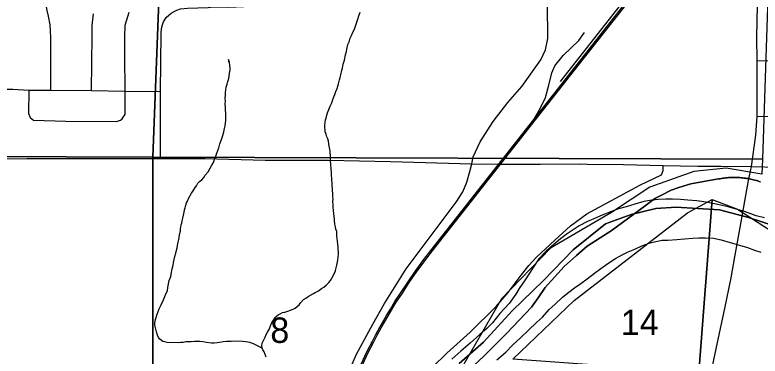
# Model space of a CAD drawing. Extents: x 0 to 34, y 0 to 22.
# Drawn here: x 3.784 to 5.012, y 16.149 to 16.711 of the extents above; entities that cross this region are included whole.
import ezdxf

# ---------------------------------------------------------------- set-up
doc = ezdxf.new("R2010")
doc.units = 0
for name, color, linetype in [('GM_X_City_Street', 7, 'Continuous'), ('GM_X_Major_River', 7, 'Continuous'), ('GM_X_Minor_River', 7, 'Continuous'), ('GM_X_Rail_Line', 7, 'Continuous'), ('GM_X_Section', 7, 'Continuous'), ('GM_X_Section_Text', 7, 'Continuous'), ('GM_X_State_Route', 7, 'Continuous'), ('GM_X_Township_Road', 7, 'Continuous'), ('SC_Shading3', 7, 'Continuous')]:
    doc.layers.add(name, color=color, linetype=linetype)

msp = doc.modelspace()

# ---------------------------------------------------------------- linework, layer by layer
at = {"layer": 'GM_X_City_Street'}
msp.add_line((4.9974, 16.4615), (5.0659, 16.4601), dxfattribs=at)
for points in [[(4.9974, 16.4615), (5.005, 16.5132), (5.007, 16.5445), (5.007, 16.6363), (5.0063, 16.6742), (5.0073, 16.7276), (5.0069, 16.7711), (5.0073, 16.8306), (5.0074, 16.8807), (5.0074, 16.9361), (5.0085, 17.0093), (5.0084, 17.0455), (5.0085, 17.0995), (5.0087, 17.1373), (5.0087, 17.1382)], [(4.5369, 16.4661), (4.5393, 16.4773), (4.5507, 16.5023), (4.572, 16.5358), (4.596, 16.5667), (4.6195, 16.5934), (4.6506, 16.6374), (4.6581, 16.6535), (4.6621, 16.6725), (4.6616, 16.729), (4.6616, 16.7781), (4.662, 16.8232), (4.6625, 16.8735), (4.661, 16.9232), (4.66, 16.9414), (4.6593, 16.9843), (4.6593, 16.9858), (4.6596, 16.9959), (4.6608, 17.0518), (4.6594, 17.1049)], [(3.8432, 16.5874), (3.8431, 16.6538), (3.8431, 16.6736), (3.8427, 16.6854), (3.8422, 16.6951), (3.8396, 16.7091), (3.8374, 16.7184), (3.8352, 16.7307), (3.8343, 16.7662), (3.8344, 16.7836)], [(4.0291, 16.7001), (4.0335, 16.707), (4.0377, 16.7109), (4.0416, 16.7143), (4.0466, 16.717), (4.051, 16.7193), (4.0571, 16.7212), (4.0682, 16.7226), (4.1026, 16.7237), (4.111, 16.7245), (4.1365, 16.7243), (4.1736, 16.7255), (4.2216, 16.7283), (4.2461, 16.7296), (4.2634, 16.7301), (4.277, 16.731), (4.2958, 16.7305), (4.3292, 16.7305), (4.4594, 16.7293), (4.5138, 16.7285), (4.6085, 16.728), (4.6616, 16.729)], [(3.9105, 16.5865), (3.9112, 16.677), (3.9112, 16.6938), (3.9134, 16.7129)], [(3.9656, 16.547), (3.9656, 16.5856), (3.9654, 16.645), (3.9654, 16.6758), (3.966, 16.6944), (3.9725, 16.7161)], [(4.0242, 16.4747), (4.0237, 16.5852), (4.0248, 16.6809), (4.0254, 16.6888), (4.0271, 16.695), (4.0291, 16.7001)], [(5.007, 16.6363), (5.0671, 16.6349), (5.1257, 16.6339), (5.1862, 16.6323)], [(3.7121, 16.589), (3.7808, 16.5888), (3.8073, 16.5874), (3.8432, 16.5874), (3.9105, 16.5865), (3.9656, 16.5856), (4.0237, 16.5852)], [(3.8073, 16.5874), (3.8064, 16.5488), (3.8091, 16.5421), (3.8145, 16.5381), (3.8678, 16.5363), (3.9513, 16.5354), (3.958, 16.5381), (3.9607, 16.5399), (3.9625, 16.543), (3.9656, 16.547)], [(5.007, 16.5445), (5.067, 16.5438), (5.0948, 16.5433), (5.1245, 16.5423), (5.184, 16.5403)], [(3.7145, 16.4741), (3.8045, 16.4747), (4.0164, 16.4747), (4.0242, 16.4747), (4.0253, 16.4747)], [(4.0253, 16.4747), (4.0971, 16.4747), (4.1964, 16.4721), (4.3009, 16.4721), (4.4028, 16.4695), (4.5369, 16.4661), (4.5828, 16.4653), (4.6502, 16.4651), (4.7147, 16.4656), (4.7267, 16.4654)], [(4.2465, 16.0051), (4.249, 16.0069), (4.2886, 16.0363), (4.3032, 16.0547), (4.3197, 16.0901), (4.3471, 16.1524), (4.3736, 16.2015), (4.3929, 16.2355), (4.4288, 16.2927), (4.511, 16.4027), (4.5218, 16.4197), (4.5289, 16.4358), (4.5336, 16.4532), (4.5369, 16.4661)], [(4.4251, 16.0847), (4.4959, 16.1536), (4.534, 16.1884), (4.5771, 16.2306), (4.5965, 16.2535), (4.6165, 16.2804), (4.6309, 16.2983), (4.6435, 16.312), (4.6737, 16.3403), (4.6992, 16.3636), (4.7262, 16.3836), (4.8134, 16.4305), (4.8494, 16.4476), (4.852, 16.4548), (4.8519, 16.4633)], [(4.7267, 16.4654), (4.7868, 16.4646), (4.8519, 16.4633), (4.9094, 16.4621), (4.9475, 16.462), (4.9974, 16.4615)], [(4.9703, 16.3128), (4.9788, 16.3607), (4.9822, 16.3797), (4.9927, 16.4385), (4.9974, 16.4615)], [(4.8397, 15.4527), (4.8456, 15.4697), (4.855, 15.5142), (4.8617, 15.5929), (4.869, 15.6599), (4.8767, 15.7363), (4.8851, 15.8274), (4.8906, 15.8858), (4.8915, 15.8956), (4.8959, 15.9365), (4.9, 15.9686), (4.9055, 15.9974), (4.9143, 16.0411), (4.9265, 16.101), (4.9418, 16.1711), (4.9536, 16.2272), (4.9641, 16.2778), (4.9703, 16.3128)]]:
    msp.add_lwpolyline(points, dxfattribs=at)
at = {"layer": 'GM_X_Major_River'}
for points in [[(5.0191, 16.3771), (5.0055, 16.3804), (4.9863, 16.3872), (4.9723, 16.3909), (4.9591, 16.395), (4.9493, 16.3971), (4.9364, 16.4), (4.9232, 16.4025), (4.9077, 16.4051), (4.8926, 16.4061), (4.8808, 16.4068), (4.8675, 16.4074), (4.8565, 16.4076), (4.8444, 16.4071), (4.8334, 16.4062), (4.8204, 16.4037), (4.8055, 16.3995), (4.791, 16.3952), (4.7785, 16.3916), (4.7655, 16.3869), (4.7517, 16.3815), (4.7379, 16.3753), (4.7276, 16.3706), (4.7138, 16.3636), (4.7019, 16.3559), (4.6923, 16.3496), (4.6827, 16.3425), (4.6722, 16.3329), (4.6591, 16.3217), (4.6471, 16.3094), (4.6366, 16.2936), (4.6248, 16.2748), (4.6147, 16.2606), (4.6092, 16.2508), (4.5983, 16.2358), (4.5831, 16.2194), (4.5711, 16.204), (4.5614, 16.1943), (4.5498, 16.1847), (4.5344, 16.1705), (4.5186, 16.1571), (4.5039, 16.1441)], [(4.5779, 16.1427), (4.5929, 16.1553), (4.6045, 16.1676), (4.6173, 16.1792), (4.6304, 16.1919), (4.6435, 16.2041), (4.6532, 16.2131), (4.6645, 16.2258), (4.6741, 16.2347), (4.6865, 16.2463), (4.6965, 16.2541), (4.7061, 16.2615), (4.7165, 16.2685), (4.7269, 16.2763), (4.7392, 16.2856), (4.7496, 16.2933), (4.7608, 16.3015), (4.7734, 16.3096), (4.7846, 16.3159), (4.7942, 16.3206), (4.8052, 16.3253), (4.8171, 16.3308), (4.8305, 16.3355), (4.84, 16.338), (4.8503, 16.34), (4.8598, 16.3402), (4.8746, 16.3411), (4.8875, 16.3424), (4.9012, 16.3436), (4.9111, 16.3438), (4.9217, 16.344), (4.935, 16.3433), (4.9478, 16.3408), (4.9625, 16.336), (4.978, 16.3319), (4.9912, 16.3278), (5.0025, 16.3238), (5.013, 16.3202)]]:
    msp.add_lwpolyline(points, dxfattribs=at)
at = {"layer": 'GM_X_Minor_River'}
for points in [[(4.3062, 16.2776), (4.3098, 16.2848), (4.3122, 16.2893), (4.3126, 16.2923), (4.3143, 16.2991), (4.316, 16.307), (4.3169, 16.3123), (4.317, 16.3169), (4.3166, 16.3283), (4.3163, 16.3336), (4.3157, 16.3386), (4.3147, 16.347), (4.3144, 16.3508), (4.3142, 16.3542), (4.3127, 16.3584), (4.3124, 16.3622), (4.3114, 16.3664), (4.3108, 16.3722), (4.3105, 16.3752), (4.3095, 16.3832), (4.3087, 16.3946), (4.3084, 16.3988), (4.3081, 16.4034), (4.3083, 16.4083), (4.308, 16.4114), (4.3077, 16.4148), (4.3075, 16.4239), (4.3069, 16.43), (4.307, 16.4338), (4.3063, 16.4388), (4.3061, 16.443), (4.3058, 16.446), (4.3056, 16.4529), (4.3049, 16.4567), (4.3047, 16.4654), (4.3041, 16.4704), (4.3042, 16.4734), (4.3039, 16.4795), (4.3033, 16.4845), (4.3034, 16.4875), (4.302, 16.4948), (4.3014, 16.4986), (4.3007, 16.5032), (4.2997, 16.507), (4.2982, 16.5101), (4.2968, 16.5147), (4.2954, 16.5185), (4.2951, 16.5219), (4.2948, 16.5253), (4.2949, 16.5284), (4.2954, 16.5341), (4.2959, 16.5382), (4.2967, 16.5413), (4.298, 16.5462), (4.2992, 16.5499), (4.3012, 16.5556), (4.3036, 16.5609), (4.3061, 16.5665), (4.3081, 16.5718), (4.3097, 16.5763), (4.3114, 16.5804), (4.3126, 16.5853), (4.315, 16.5902), (4.3162, 16.594), (4.3171, 16.5978), (4.3188, 16.6042), (4.32, 16.608), (4.3213, 16.6125), (4.3226, 16.6204), (4.3238, 16.6234), (4.3251, 16.6299), (4.3272, 16.637), (4.3289, 16.6457), (4.3306, 16.651), (4.3311, 16.6548), (4.3328, 16.6624), (4.3352, 16.668), (4.336, 16.6718), (4.3385, 16.6774), (4.3413, 16.6842), (4.3433, 16.688), (4.3474, 16.6993), (4.349, 16.7042), (4.3507, 16.7098), (4.3527, 16.7159)], [(4.1313, 16.5579), (4.1307, 16.5655), (4.1308, 16.5685), (4.1306, 16.5743), (4.1311, 16.5792), (4.1312, 16.5834), (4.1321, 16.5925), (4.1338, 16.5974), (4.135, 16.6015), (4.1363, 16.6064), (4.1372, 16.6106), (4.1376, 16.6151), (4.1385, 16.62), (4.1386, 16.6238), (4.1384, 16.6284), (4.1377, 16.633), (4.1359, 16.638), (4.1361, 16.6335)], [(4.1915, 16.1622), (4.1773, 16.1694), (4.1712, 16.1715), (4.1648, 16.1724), (4.1595, 16.1729), (4.1454, 16.1733), (4.1405, 16.173), (4.1325, 16.1728), (4.1271, 16.1722), (4.1214, 16.1712), (4.1172, 16.1709), (4.1123, 16.1703), (4.1081, 16.1704), (4.0997, 16.1714), (4.0937, 16.1723), (4.0887, 16.1728), (4.08, 16.173), (4.0747, 16.1727), (4.069, 16.1725), (4.0655, 16.1722), (4.0613, 16.1715), (4.0575, 16.1713), (4.0545, 16.171), (4.0347, 16.1714), (4.0309, 16.1723), (4.0279, 16.1728), (4.023, 16.1767), (4.0208, 16.1798), (4.019, 16.1832), (4.0173, 16.189), (4.0155, 16.1955), (4.0145, 16.2001), (4.0146, 16.2039), (4.0155, 16.2095), (4.0184, 16.2182), (4.022, 16.2269), (4.0252, 16.2336), (4.0288, 16.2415), (4.0324, 16.2498), (4.0353, 16.2573), (4.0358, 16.2619), (4.0384, 16.2736), (4.0412, 16.28), (4.0416, 16.2838), (4.043, 16.2929), (4.0451, 16.2989), (4.0456, 16.3034), (4.0477, 16.3129), (4.0493, 16.3186), (4.0498, 16.3216), (4.0515, 16.3276), (4.0519, 16.331), (4.0532, 16.3367), (4.0541, 16.3409), (4.0545, 16.3439), (4.0554, 16.3496), (4.0567, 16.3549), (4.0568, 16.3587), (4.0581, 16.3651), (4.0589, 16.3681), (4.0598, 16.3719), (4.0607, 16.3764), (4.0619, 16.3813), (4.0628, 16.3863), (4.0637, 16.39), (4.0645, 16.3934), (4.0657, 16.3976), (4.067, 16.4014), (4.0686, 16.4044), (4.0702, 16.4085), (4.075, 16.4175), (4.0777, 16.4216), (4.0813, 16.4269), (4.0833, 16.4298), (4.0857, 16.434), (4.0884, 16.4369), (4.0919, 16.4395), (4.0954, 16.4432), (4.0978, 16.447), (4.1025, 16.4529), (4.106, 16.4589), (4.1084, 16.4638), (4.1112, 16.4679), (4.1137, 16.4747), (4.1153, 16.4785), (4.1169, 16.4837), (4.1185, 16.4879), (4.1202, 16.4924), (4.1219, 16.4988), (4.1243, 16.506), (4.1264, 16.5128), (4.1281, 16.5188), (4.1293, 16.5241), (4.1306, 16.5286), (4.131, 16.5324), (4.1316, 16.5377), (4.1317, 16.5419), (4.1318, 16.5465), (4.1315, 16.5495), (4.1312, 16.5541), (4.1313, 16.5579)], [(4.198, 16.1473), (4.1948, 16.1557), (4.1926, 16.1592), (4.1915, 16.1622), (4.1909, 16.1657), (4.1917, 16.1702), (4.1946, 16.1766), (4.1965, 16.1804), (4.1982, 16.1845), (4.2002, 16.1886), (4.2033, 16.1939), (4.2054, 16.1988), (4.2078, 16.2052), (4.2106, 16.2089), (4.2125, 16.2123), (4.2176, 16.2167), (4.2211, 16.2185), (4.2249, 16.2207), (4.2287, 16.2214), (4.2353, 16.2235), (4.2383, 16.2246), (4.2426, 16.2264), (4.246, 16.2282), (4.2522, 16.2333), (4.2554, 16.2374), (4.2593, 16.2423), (4.2643, 16.2448), (4.2674, 16.247), (4.2759, 16.2521), (4.279, 16.254), (4.284, 16.2565), (4.289, 16.2606), (4.2933, 16.2624), (4.2975, 16.2664), (4.3011, 16.2705), (4.3038, 16.2735), (4.3062, 16.2776)]]:
    msp.add_lwpolyline(points, dxfattribs=at)
at = {"layer": 'GM_X_Rail_Line'}
for points in [[(4.3543, 16.1358), (4.3639, 16.1559), (4.3731, 16.1736), (4.3789, 16.1845), (4.3854, 16.1966), (4.3962, 16.2157), (4.4027, 16.2262), (4.4102, 16.239), (4.4194, 16.2526), (4.4318, 16.2716), (4.4445, 16.29), (4.4578, 16.3081), (4.4696, 16.3232), (4.7042, 16.6217), (4.8478, 16.8047), (4.9534, 16.9393), (5.0803, 17.1004), (5.1191, 17.1499), (5.1842, 17.233), (5.3027, 17.3835), (5.4259, 17.5407), (5.4633, 17.5884)], [(5.1421, 17.1875), (5.1385, 17.1817), (5.1284, 17.1679), (4.9398, 16.929), (4.7753, 16.7196), (4.6823, 16.6015)], [(4.3565, 16.1348), (4.3662, 16.1548), (4.3753, 16.1724), (4.3811, 16.1833), (4.3876, 16.1954), (4.3983, 16.2144), (4.4048, 16.2249), (4.4123, 16.2376), (4.4214, 16.2512), (4.4339, 16.2702), (4.4465, 16.2886), (4.4598, 16.3066), (4.4715, 16.3217), (4.7062, 16.6202), (4.8497, 16.8032), (4.9554, 16.9378), (5.0823, 17.0989)], [(4.6391, 16.5389), (4.6494, 16.557), (4.6585, 16.575), (4.6637, 16.5955), (4.6689, 16.616), (4.6736, 16.6276), (4.6871, 16.6443), (4.713, 16.669), (4.7226, 16.6821)]]:
    msp.add_lwpolyline(points, dxfattribs=at)
at = {"layer": 'GM_X_Section'}
for points in [[(3.0196, 17.4831), (3.1709, 17.4714), (4.0485, 17.4495), (4.0113, 16.4768), (3.0135, 16.4807)], [(4.0485, 17.4495), (5.0461, 17.3925), (5.016, 16.4735), (4.0113, 16.4768)], [(3.0135, 16.4807), (4.0113, 16.4768), (4.0112, 15.46), (3.0168, 15.4789)], [(4.0113, 16.4768), (5.016, 16.4735), (5.0144, 16.4489), (4.9559, 16.4588), (4.9027, 16.4533), (4.8303, 16.4274), (4.767, 16.3854), (4.6663, 16.3267), (4.586, 16.2434), (4.5198, 16.1291), (4.4237, 16.0287), (4.3302, 15.9111), (4.264, 15.7957), (4.2171, 15.6985), (4.1382, 15.5716), (4.0543, 15.4588), (4.0112, 15.46)], [(4.6046, 16.1438), (4.7052, 16.2404), (4.8924, 16.385), (4.9329, 16.4073), (4.9109, 16.1221)], [(4.9329, 16.4073), (4.9747, 16.391), (5.0349, 16.3524), (5.1555, 16.2978), (5.2124, 16.265), (5.3126, 16.2343), (5.437, 16.2217), (5.569, 16.217), (5.709, 16.1875), (5.8473, 16.1527), (5.9234, 16.1293), (5.9113, 16.0496), (4.9109, 16.1221)]]:
    msp.add_lwpolyline(points, close=True, dxfattribs=at)
at = {"layer": 'GM_X_State_Route'}
msp.add_lwpolyline([(4.5218, 16.1162), (4.5574, 16.1495), (4.5664, 16.1585), (4.5944, 16.1865), (4.635, 16.2298), (4.6459, 16.2452), (4.6578, 16.2621), (4.6788, 16.2853), (4.689, 16.2965), (4.7094, 16.3146), (4.7271, 16.3304), (4.7482, 16.344), (4.7662, 16.3555), (4.8227, 16.3968), (4.8318, 16.4035), (4.8397, 16.4093), (4.8491, 16.4141), (4.8655, 16.4225), (4.8779, 16.4266), (4.8979, 16.4331), (4.9337, 16.4393), (4.9433, 16.4409), (4.9458, 16.4414), (4.9481, 16.4418), (4.9504, 16.4421), (4.9527, 16.4424), (4.955, 16.4427), (4.9573, 16.4429), (4.9596, 16.4431), (4.9619, 16.4433), (4.9642, 16.4434), (4.9666, 16.4434), (4.9689, 16.4435), (4.9712, 16.4434), (4.9735, 16.4434), (4.9759, 16.4433), (4.9782, 16.4431), (4.9805, 16.443), (4.9828, 16.4428), (4.9851, 16.4425), (4.9858, 16.4424), (4.9874, 16.4422), (4.9879, 16.4421), (4.9897, 16.4419), (4.9899, 16.4418), (4.992, 16.4415), (4.9943, 16.4411), (4.9959, 16.4407), (4.9962, 16.4407), (4.9966, 16.4406), (4.9988, 16.4401), (5.0009, 16.4396), (5.0011, 16.4396), (5.0033, 16.439), (5.0056, 16.4384), (5.0078, 16.4377), (5.01, 16.437), (5.0122, 16.4363)], dxfattribs=at)
at = {"layer": 'GM_X_Township_Road'}
for points in [[(4.516, 16.137), (4.5563, 16.1721), (4.6034, 16.2236), (4.6549, 16.2733), (4.7038, 16.3239), (4.757, 16.3668), (4.7993, 16.3826), (4.84, 16.3925), (4.8735, 16.3942), (4.9447, 16.3899), (4.982, 16.3803), (4.991, 16.3779), (5.0467, 16.3599)], [(5.0467, 16.3599), (4.991, 16.3779), (4.982, 16.3803), (4.9447, 16.3899), (4.8735, 16.3942), (4.84, 16.3925), (4.7993, 16.3826), (4.757, 16.3668), (4.7038, 16.3239), (4.6549, 16.2733), (4.6034, 16.2236), (4.5563, 16.1721), (4.516, 16.137)]]:
    msp.add_lwpolyline(points, dxfattribs=at)
at = {"layer": 'SC_Shading3'}
msp.add_lwpolyline([(5.0122, 16.4363), (5.01, 16.437), (5.0078, 16.4377), (5.0056, 16.4384), (5.0033, 16.439), (5.0011, 16.4396), (5.0009, 16.4396), (4.9988, 16.4401), (4.9966, 16.4406), (4.9962, 16.4407), (4.9959, 16.4407), (4.9943, 16.4411), (4.992, 16.4415), (4.9899, 16.4418), (4.9897, 16.4419), (4.9879, 16.4421), (4.9874, 16.4422), (4.9858, 16.4424), (4.9851, 16.4425), (4.9828, 16.4428), (4.9805, 16.443), (4.9782, 16.4431), (4.9759, 16.4433), (4.9735, 16.4434), (4.9712, 16.4434), (4.9689, 16.4435), (4.9666, 16.4434), (4.9642, 16.4434), (4.9619, 16.4433), (4.9596, 16.4431), (4.9573, 16.4429), (4.955, 16.4427), (4.9527, 16.4424), (4.9504, 16.4421), (4.9481, 16.4418), (4.9458, 16.4414), (4.9433, 16.4409), (4.9337, 16.4393), (4.8979, 16.4331), (4.8779, 16.4266), (4.8655, 16.4225), (4.8491, 16.4141), (4.8397, 16.4093), (4.8318, 16.4035), (4.8227, 16.3968), (4.7662, 16.3555), (4.7482, 16.344), (4.7271, 16.3304), (4.7094, 16.3146), (4.689, 16.2965), (4.6788, 16.2853), (4.6578, 16.2621), (4.6459, 16.2452), (4.635, 16.2298), (4.5944, 16.1865), (4.5664, 16.1585), (4.5574, 16.1495), (4.5218, 16.1162)], dxfattribs=at)

# ---------------------------------------------------------------- texts
at = {"layer": 'GM_X_Section_Text'}
for s, height, p in [('14', 0.04186, (4.7824, 16.1836)), ('8', 0.0419, (4.2049, 16.1707))]:
    msp.add_text(s, height=height, rotation=0, dxfattribs=at).set_placement(p)

doc.saveas('drawing.dxf')
